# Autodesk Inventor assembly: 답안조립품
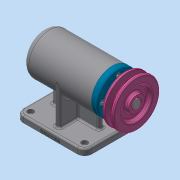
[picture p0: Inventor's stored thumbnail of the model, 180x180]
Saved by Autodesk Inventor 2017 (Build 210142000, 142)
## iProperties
Part Number: 답안조립품
Material: 일반
Document SubType Name: Assembly
Designer: mrc
Author: mrc
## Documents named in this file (12)
- C:\Users\mrc\Desktop\701004V1022\답안조립품.iam
- C:\Users\mrc\Desktop\701004V1022\본체.ipt
- C:\Users\mrc\Desktop\701004V1022\V벨트풀리.ipt
- C:\Users\mrc\Desktop\701004V1022\멈춤나사 M3.ipt
- C:\Users\mrc\Desktop\701004V1022\베어링 6004.ipt
- C:\Users\mrc\Desktop\701004V1022\베어링 51202.ipt
- C:\Users\mrc\Desktop\701004V1022\볼트 M4.ipt
- C:\Users\mrc\Desktop\701004V1022\어댑터슬리브.ipt
- C:\Users\mrc\Desktop\701004V1022\오일 실.ipt
- C:\Users\mrc\Desktop\701004V1022\축.ipt
- C:\Users\mrc\Desktop\701004V1022\커버.ipt
- C:\Users\mrc\Desktop\701004V1022\키 5 x 5 x 16.ipt
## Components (1 placed, 1 different names)
1. V벨트풀리:1 — 플러쉬:2
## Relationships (1: Flush 1)
- 플러쉬:2 [Flush]: V벨트풀리:1
